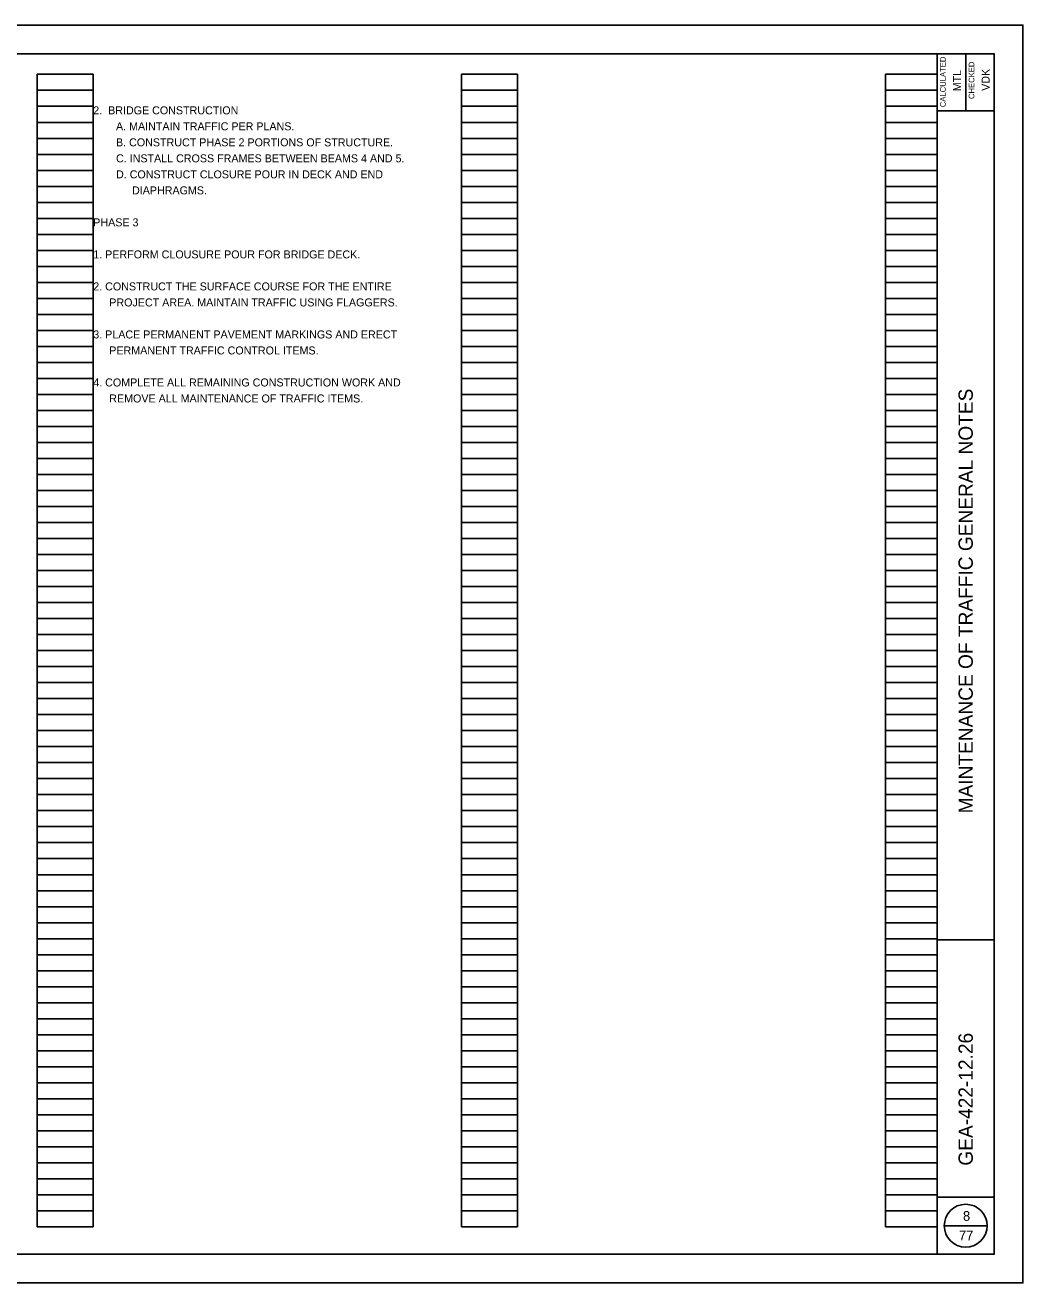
# Model space of a CAD drawing. Extents: x 0 to 34, y 0 to 22.
# Drawn here: x 16.55 to 34, y 0 to 22 of the extents above; entities that cross this region are included whole.
import ezdxf

# ---------------------------------------------------------------- set-up
doc = ezdxf.new("R2010")
doc.units = 0
for name, color, linetype in [('SC_Scratch1', 7, 'Continuous'), ('SH_Border', 7, 'Continuous'), ('SH_Cut_Line', 7, 'Continuous'), ('SH_Data', 7, 'Continuous'), ('SH_Text', 7, 'Continuous')]:
    doc.layers.add(name, color=color, linetype=linetype)

msp = doc.modelspace()

# ---------------------------------------------------------------- linework, layer by layer
at = {"layer": 'SC_Scratch1'}
for p, q in [((16.76, 0.98), (16.76, 21.14)), ((16.76, 21.14), (17.74, 21.14)), ((17.74, 0.98), (17.74, 21.14)), ((24.18, 0.98), (24.18, 21.14)), ((24.18, 21.14), (25.16, 21.14)), ((25.16, 0.98), (25.16, 21.14)), ((31.6, 0.98), (31.6, 21.14)), ((31.6, 21.14), (32.5, 21.14)), ((32.5, 0.98), (32.5, 21.14)), ((16.76, 20.86), (17.74, 20.86)), ((24.18, 20.86), (25.16, 20.86)), ((31.6, 20.86), (32.5, 20.86)), ((16.76, 20.58), (17.74, 20.58)), ((24.18, 20.58), (25.16, 20.58)), ((31.6, 20.58), (32.5, 20.58)), ((16.76, 20.3), (17.74, 20.3)), ((24.18, 20.3), (25.16, 20.3)), ((31.6, 20.3), (32.5, 20.3)), ((16.76, 20.02), (17.74, 20.02)), ((24.18, 20.02), (25.16, 20.02)), ((31.6, 20.02), (32.5, 20.02)), ((16.76, 19.74), (17.74, 19.74)), ((24.18, 19.74), (25.16, 19.74)), ((31.6, 19.74), (32.5, 19.74)), ((16.76, 19.46), (17.74, 19.46)), ((24.18, 19.46), (25.16, 19.46)), ((31.6, 19.46), (32.5, 19.46)), ((16.76, 19.18), (17.74, 19.18)), ((24.18, 19.18), (25.16, 19.18)), ((31.6, 19.18), (32.5, 19.18)), ((16.76, 18.9), (17.74, 18.9)), ((24.18, 18.9), (25.16, 18.9)), ((31.6, 18.9), (32.5, 18.9)), ((16.76, 18.62), (17.74, 18.62)), ((24.18, 18.62), (25.16, 18.62)), ((31.6, 18.62), (32.5, 18.62)), ((16.76, 18.34), (17.74, 18.34)), ((24.18, 18.34), (25.16, 18.34)), ((31.6, 18.34), (32.5, 18.34)), ((16.76, 18.06), (17.74, 18.06)), ((24.18, 18.06), (25.16, 18.06)), ((31.6, 18.06), (32.5, 18.06)), ((16.76, 17.78), (17.74, 17.78)), ((24.18, 17.78), (25.16, 17.78)), ((31.6, 17.78), (32.5, 17.78)), ((16.76, 17.5), (17.74, 17.5)), ((24.18, 17.5), (25.16, 17.5)), ((31.6, 17.5), (32.5, 17.5)), ((16.76, 17.22), (17.74, 17.22)), ((24.18, 17.22), (25.16, 17.22)), ((31.6, 17.22), (32.5, 17.22)), ((16.76, 16.94), (17.74, 16.94)), ((24.18, 16.94), (25.16, 16.94)), ((31.6, 16.94), (32.5, 16.94)), ((16.76, 16.66), (17.74, 16.66)), ((24.18, 16.66), (25.16, 16.66)), ((31.6, 16.66), (32.5, 16.66)), ((16.76, 16.38), (17.74, 16.38)), ((24.18, 16.38), (25.16, 16.38)), ((31.6, 16.38), (32.5, 16.38)), ((16.76, 16.1), (17.74, 16.1)), ((24.18, 16.1), (25.16, 16.1)), ((31.6, 16.1), (32.5, 16.1)), ((16.76, 15.82), (17.74, 15.82)), ((24.18, 15.82), (25.16, 15.82)), ((31.6, 15.82), (32.5, 15.82)), ((16.76, 15.54), (17.74, 15.54)), ((24.18, 15.54), (25.16, 15.54)), ((31.6, 15.54), (32.5, 15.54)), ((16.76, 15.26), (17.74, 15.26)), ((24.18, 15.26), (25.16, 15.26)), ((31.6, 15.26), (32.5, 15.26)), ((16.76, 14.98), (17.74, 14.98)), ((24.18, 14.98), (25.16, 14.98)), ((31.6, 14.98), (32.5, 14.98)), ((16.76, 14.7), (17.74, 14.7)), ((24.18, 14.7), (25.16, 14.7)), ((31.6, 14.7), (32.5, 14.7)), ((16.76, 14.42), (17.74, 14.42)), ((24.18, 14.42), (25.16, 14.42)), ((31.6, 14.42), (32.5, 14.42)), ((16.76, 14.14), (17.74, 14.14)), ((24.18, 14.14), (25.16, 14.14)), ((31.6, 14.14), (32.5, 14.14)), ((16.76, 13.86), (17.74, 13.86)), ((24.18, 13.86), (25.16, 13.86)), ((31.6, 13.86), (32.5, 13.86)), ((16.76, 13.58), (17.74, 13.58)), ((24.18, 13.58), (25.16, 13.58)), ((31.6, 13.58), (32.5, 13.58)), ((16.76, 13.3), (17.74, 13.3)), ((24.18, 13.3), (25.16, 13.3)), ((31.6, 13.3), (32.5, 13.3)), ((16.76, 13.02), (17.74, 13.02)), ((24.18, 13.02), (25.16, 13.02)), ((31.6, 13.02), (32.5, 13.02)), ((16.76, 12.74), (17.74, 12.74)), ((24.18, 12.74), (25.16, 12.74)), ((31.6, 12.74), (32.5, 12.74)), ((16.76, 12.46), (17.74, 12.46)), ((24.18, 12.46), (25.16, 12.46)), ((31.6, 12.46), (32.5, 12.46)), ((16.76, 12.18), (17.74, 12.18)), ((24.18, 12.18), (25.16, 12.18)), ((31.6, 12.18), (32.5, 12.18)), ((16.76, 11.9), (17.74, 11.9)), ((24.18, 11.9), (25.16, 11.9)), ((31.6, 11.9), (32.5, 11.9)), ((16.76, 11.62), (17.74, 11.62)), ((24.18, 11.62), (25.16, 11.62)), ((31.6, 11.62), (32.5, 11.62)), ((16.76, 11.34), (17.74, 11.34)), ((24.18, 11.34), (25.16, 11.34)), ((31.6, 11.34), (32.5, 11.34)), ((16.76, 11.06), (17.74, 11.06)), ((24.18, 11.06), (25.16, 11.06)), ((31.6, 11.06), (32.5, 11.06)), ((16.76, 10.78), (17.74, 10.78)), ((24.18, 10.78), (25.16, 10.78)), ((31.6, 10.78), (32.5, 10.78)), ((16.76, 10.5), (17.74, 10.5)), ((24.18, 10.5), (25.16, 10.5)), ((31.6, 10.5), (32.5, 10.5)), ((16.76, 10.22), (17.74, 10.22)), ((24.18, 10.22), (25.16, 10.22)), ((31.6, 10.22), (32.5, 10.22)), ((16.76, 9.94), (17.74, 9.94)), ((24.18, 9.94), (25.16, 9.94)), ((31.6, 9.94), (32.5, 9.94)), ((16.76, 9.66), (17.74, 9.66)), ((24.18, 9.66), (25.16, 9.66)), ((31.6, 9.66), (32.5, 9.66)), ((16.76, 9.38), (17.74, 9.38)), ((24.18, 9.38), (25.16, 9.38)), ((31.6, 9.38), (32.5, 9.38)), ((16.76, 9.1), (17.74, 9.1)), ((24.18, 9.1), (25.16, 9.1)), ((31.6, 9.1), (32.5, 9.1)), ((16.76, 8.82), (17.74, 8.82)), ((24.18, 8.82), (25.16, 8.82)), ((31.6, 8.82), (32.5, 8.82)), ((16.76, 8.54), (17.74, 8.54)), ((24.18, 8.54), (25.16, 8.54)), ((31.6, 8.54), (32.5, 8.54)), ((16.76, 8.26), (17.74, 8.26)), ((24.18, 8.26), (25.16, 8.26)), ((31.6, 8.26), (32.5, 8.26)), ((16.76, 7.98), (17.74, 7.98)), ((24.18, 7.98), (25.16, 7.98)), ((31.6, 7.98), (32.5, 7.98)), ((16.76, 7.7), (17.74, 7.7)), ((24.18, 7.7), (25.16, 7.7)), ((31.6, 7.7), (32.5, 7.7)), ((16.76, 7.42), (17.74, 7.42)), ((24.18, 7.42), (25.16, 7.42)), ((31.6, 7.42), (32.5, 7.42)), ((16.76, 7.14), (17.74, 7.14)), ((24.18, 7.14), (25.16, 7.14)), ((31.6, 7.14), (32.5, 7.14)), ((16.76, 6.86), (17.74, 6.86)), ((24.18, 6.86), (25.16, 6.86)), ((31.6, 6.86), (32.5, 6.86)), ((16.76, 6.58), (17.74, 6.58)), ((24.18, 6.58), (25.16, 6.58)), ((31.6, 6.58), (32.5, 6.58)), ((16.76, 6.3), (17.74, 6.3)), ((24.18, 6.3), (25.16, 6.3)), ((31.6, 6.3), (32.5, 6.3)), ((16.76, 6.02), (17.74, 6.02)), ((24.18, 6.02), (25.16, 6.02)), ((31.6, 6.02), (32.5, 6.02)), ((16.76, 5.74), (17.74, 5.74)), ((24.18, 5.74), (25.16, 5.74)), ((31.6, 5.74), (32.5, 5.74)), ((16.76, 5.46), (17.74, 5.46)), ((24.18, 5.46), (25.16, 5.46)), ((31.6, 5.46), (32.5, 5.46)), ((16.76, 5.18), (17.74, 5.18)), ((24.18, 5.18), (25.16, 5.18)), ((31.6, 5.18), (32.5, 5.18)), ((16.76, 4.9), (17.74, 4.9)), ((24.18, 4.9), (25.16, 4.9)), ((31.6, 4.9), (32.5, 4.9)), ((16.76, 4.62), (17.74, 4.62)), ((24.18, 4.62), (25.16, 4.62)), ((31.6, 4.62), (32.5, 4.62)), ((16.76, 4.34), (17.74, 4.34)), ((24.18, 4.34), (25.16, 4.34)), ((31.6, 4.34), (32.5, 4.34)), ((16.76, 4.06), (17.74, 4.06)), ((24.18, 4.06), (25.16, 4.06)), ((31.6, 4.06), (32.5, 4.06)), ((16.76, 3.78), (17.74, 3.78)), ((24.18, 3.78), (25.16, 3.78)), ((31.6, 3.78), (32.5, 3.78)), ((16.76, 3.5), (17.74, 3.5)), ((24.18, 3.5), (25.16, 3.5)), ((31.6, 3.5), (32.5, 3.5)), ((16.76, 3.22), (17.74, 3.22)), ((24.18, 3.22), (25.16, 3.22)), ((31.6, 3.22), (32.5, 3.22)), ((16.76, 2.94), (17.74, 2.94)), ((24.18, 2.94), (25.16, 2.94)), ((31.6, 2.94), (32.5, 2.94)), ((16.76, 2.66), (17.74, 2.66)), ((24.18, 2.66), (25.16, 2.66)), ((31.6, 2.66), (32.5, 2.66)), ((16.76, 2.38), (17.74, 2.38)), ((24.18, 2.38), (25.16, 2.38)), ((31.6, 2.38), (32.5, 2.38)), ((16.76, 2.1), (17.74, 2.1)), ((24.18, 2.1), (25.16, 2.1)), ((31.6, 2.1), (32.5, 2.1)), ((16.76, 1.82), (17.74, 1.82)), ((24.18, 1.82), (25.16, 1.82)), ((31.6, 1.82), (32.5, 1.82)), ((16.76, 1.54), (17.74, 1.54)), ((24.18, 1.54), (25.16, 1.54)), ((31.6, 1.54), (32.5, 1.54)), ((16.76, 1.26), (17.74, 1.26)), ((24.18, 1.26), (25.16, 1.26)), ((31.6, 1.26), (32.5, 1.26)), ((16.76, 0.98), (17.74, 0.98)), ((24.18, 0.98), (25.16, 0.98)), ((31.6, 0.98), (32.5, 0.98))]:
    msp.add_line(p, q, dxfattribs=at)
at = {"layer": 'SH_Border'}
for p, q in [((32.5, 0.5), (32.5, 21.5)), ((33, 21.5), (33, 20.5)), ((32.5, 20.5), (33.5, 20.5)), ((32.5, 6), (33.5, 6)), ((32.5, 1.5), (33.5, 1.5))]:
    msp.add_line(p, q, dxfattribs=at)
msp.add_lwpolyline([(2, 21.5), (33.5, 21.5), (33.5, 0.5), (2, 0.5)], close=True, dxfattribs=at)
at = {"layer": 'SH_Cut_Line'}
msp.add_lwpolyline([(0, 0), (34, 0), (34, 22), (0, 22)], close=True, dxfattribs=at)
at = {"layer": 'SH_Data'}
msp.add_line((32.625, 1), (33.375, 1), dxfattribs=at)
msp.add_circle((33, 1), 0.375, dxfattribs=at)

# ---------------------------------------------------------------- texts
for s, height, p in [('CALCULATED', 0.1, (32.652, 20.565)), ('CHECKED', 0.1, (33.152, 20.708)), ('MTL', 0.14, (32.92, 20.844)), ('VDK', 0.14, (33.42, 20.851)), ('MAINTENANCE OF TRAFFIC GENERAL NOTES', 0.25, (33.125, 8.212)), (' GEA-422-12.26 ', 0.25, (33.125, 1.957))]:
    msp.add_text(s, height=height, rotation=90, dxfattribs=at).set_placement(p)
for s, p in [('8', (32.953, 1.085)), ('77', (32.882, 0.745))]:
    msp.add_text(s, height=0.17, dxfattribs=at).set_placement(p)
at = {"layer": 'SH_Text'}
for s, p in [('2.  BRIDGE CONSTRUCTION', (17.74, 20.44)), ('A. MAINTAIN TRAFFIC PER PLANS.', (18.138, 20.16)), ('B. CONSTRUCT PHASE 2 PORTIONS OF STRUCTURE.', (18.138, 19.88)), ('C. INSTALL CROSS FRAMES BETWEEN BEAMS 4 AND 5.', (18.138, 19.6)), ('D. CONSTRUCT CLOSURE POUR IN DECK AND END ', (18.138, 19.32)), ('DIAPHRAGMS.', (18.418, 19.04)), ('PHASE 3', (17.74, 18.48)), ('1. PERFORM CLOUSURE POUR FOR BRIDGE DECK.', (17.74, 17.92)), ('2. CONSTRUCT THE SURFACE COURSE FOR THE ENTIRE ', (17.74, 17.36)), ('PROJECT AREA. MAINTAIN TRAFFIC USING FLAGGERS.', (18.02, 17.08)), ('3. PLACE PERMANENT PAVEMENT MARKINGS AND ERECT ', (17.74, 16.52)), ('PERMANENT TRAFFIC CONTROL ITEMS.', (18.02, 16.24)), ('4. COMPLETE ALL REMAINING CONSTRUCTION WORK AND ', (17.74, 15.68)), ('REMOVE ALL MAINTENANCE OF TRAFFIC ITEMS.', (18.02, 15.4))]:
    msp.add_text(s, height=0.14, dxfattribs=at).set_placement(p)

doc.saveas('drawing.dxf')
